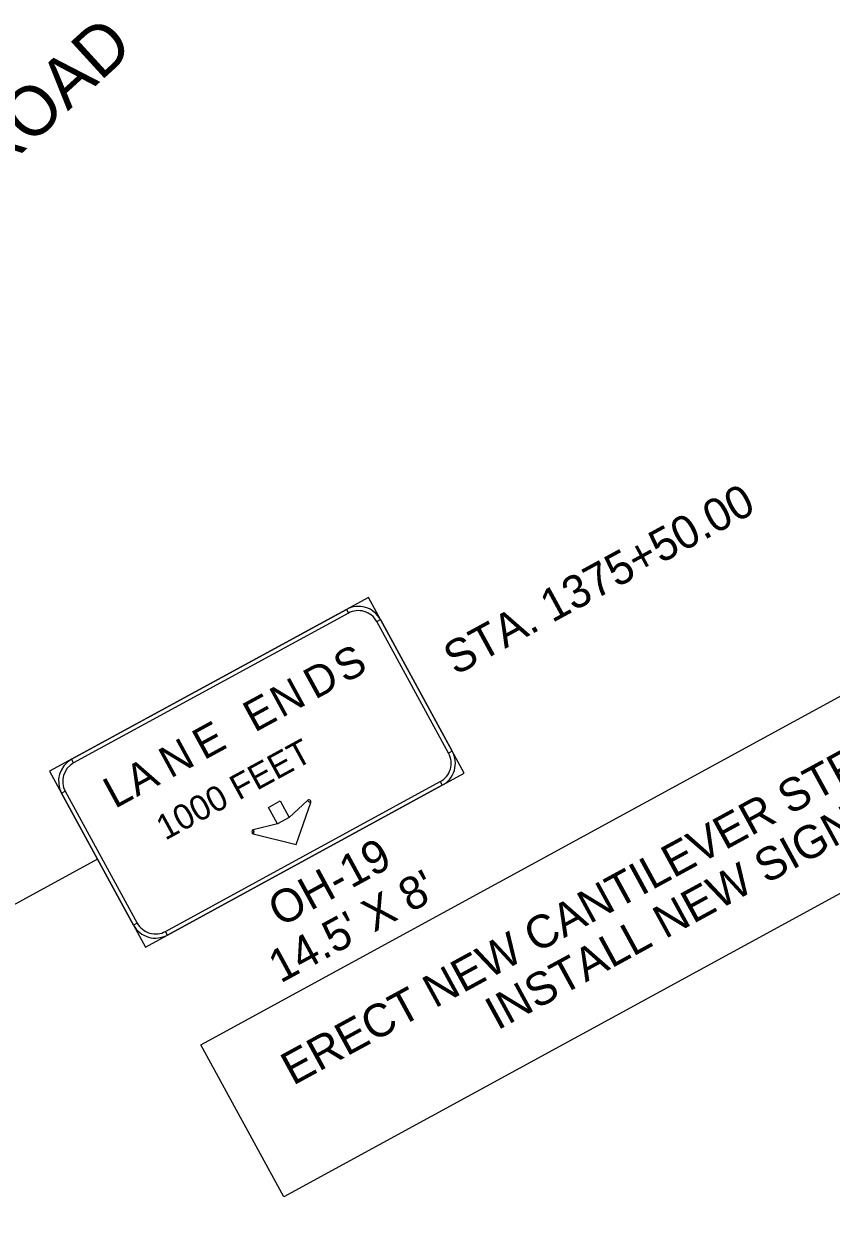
# Model space of a CAD drawing. Extents: x 2001876 to 2025694, y 804561 to 868938.
# Drawn here: x 2013356 to 2013846, y 824313 to 825035 of the extents above; entities that cross this region are included whole.
import ezdxf

# ---------------------------------------------------------------- set-up
doc = ezdxf.new("R2010")
doc.units = 0
for name, color, linetype in [('RD_TX_RoadID', 7, 'Continuous'), ('TR SN EXTRUDED PANEL SIGNS - GROUND MOUNTED', 7, 'Continuous'), ('TR SN EXTRUDED PANEL SIGNS- MOUNTED OVERHEAD', 7, 'Continuous')]:
    doc.layers.add(name, color=color, linetype=linetype)

msp = doc.modelspace()

# ---------------------------------------------------------------- linework, layer by layer
at = {"layer": 'TR SN EXTRUDED PANEL SIGNS - GROUND MOUNTED'}
for p, q in [((2013551.97, 824679.38), (2013553.18, 824677.16)), ((2013570.37, 824672.1), (2013572.59, 824673.31)), ((2013616.26, 824593.25), (2013614.04, 824592.04)), ((2013386.38, 824586.17), (2013385.17, 824588.4)), ((2013608.99, 824574.85), (2013610.2, 824572.63)), ((2013379.1, 824567.77), (2013381.33, 824568.99)), ((2013528.28, 824563.43), (2013529.15, 824562.51)), ((2013529.15, 824562.51), (2013530.35, 824562.11)), ((2013495.47, 824543.08), (2013495.79, 824544.31)), ((2013495.79, 824544.31), (2013495.48, 824545.54)), ((2013400.94, 824527.74), (2012949.03, 824281.24)), ((2013425, 824488.92), (2013422.78, 824487.71)), ((2013443.4, 824481.65), (2013442.18, 824483.87))]:
    msp.add_line(p, q, dxfattribs=at)
for points in [[(2013430.05, 824474.37), (2013623.54, 824579.91), (2013565.31, 824686.66), (2013371.83, 824581.12), (2013430.05, 824474.37)], [(2013553.18, 824677.16), (2013386.38, 824586.17), (2013385.17, 824588.4), (2013551.97, 824679.38), (2013553.18, 824677.16)], [(2013614.04, 824592.04), (2013570.37, 824672.1), (2013572.59, 824673.31), (2013616.26, 824593.25), (2013614.04, 824592.04)], [(2013442.18, 824483.87), (2013608.99, 824574.85), (2013610.2, 824572.63), (2013443.4, 824481.65), (2013442.18, 824483.87)], [(2013381.33, 824568.99), (2013425, 824488.92), (2013422.78, 824487.71), (2013379.1, 824567.77), (2013381.33, 824568.99)], [(2013521.57, 824536.73), (2013530.35, 824562.11), (2013529.15, 824562.51), (2013528.28, 824563.43), (2013517.3, 824553.15), (2013510.07, 824549.21), (2013495.48, 824545.54), (2013495.79, 824544.31), (2013495.47, 824543.08), (2013521.57, 824536.73)], [(2013504.61, 824559.22), (2013511.84, 824563.16), (2013517.3, 824553.15), (2013510.07, 824549.21), (2013504.61, 824559.22)]]:
    msp.add_lwpolyline(points, close=True, dxfattribs=at)
for centre, radius, start, end in [((2013559.25, 824666.04), 15.2, 28.61049, 118.6107), ((2013559.25, 824666.04), 12.67, 28.61049, 118.6107), ((2013602.92, 824585.97), 12.67, 298.61055, 28.61076), ((2013602.92, 824585.97), 15.2, 298.61055, 28.61076), ((2013392.45, 824575.05), 15.2, 118.6107, 208.61034), ((2013392.45, 824575.05), 12.67, 118.6107, 208.61034), ((2013529.15, 824562.51), 1.27, 341.63567, 133.08331), ((2013495.79, 824544.31), 1.27, 104.13779, 255.58543), ((2013436.12, 824494.99), 15.2, 208.61034, 298.61055), ((2013436.12, 824494.99), 12.67, 208.61034, 298.61055)]:
    msp.add_arc(centre, radius, start, end, dxfattribs=at)
at = {"layer": 'TR SN EXTRUDED PANEL SIGNS- MOUNTED OVERHEAD'}
msp.add_lwpolyline([(2013463.57, 824415.02), (2014004.74, 824710.2), (2014055.15, 824617.78), (2013513.98, 824322.6)], close=True, dxfattribs=at)

# ---------------------------------------------------------------- texts
at = {"layer": 'RD_TX_RoadID'}
msp.add_text('NORFOLK SOUTHERN RAILROAD', height=30, rotation=42.37827, dxfattribs=at).set_placement((2012946.49, 824583.75))
at = {"layer": 'TR SN EXTRUDED PANEL SIGNS - GROUND MOUNTED'}
for s, height, p in [('S', 19, (2013551.02, 824634.31)), ('D', 19, (2013532.93, 824624.44)), ('N', 19, (2013512.57, 824613.34)), ('E', 19, (2013496.27, 824604.45)), ('E', 19, (2013465.51, 824587.67)), ('1000 FEET', 15.2, (2013441.99, 824538.89)), ('N', 19, (2013445.15, 824576.57)), ('A', 19, (2013424.7, 824565.41)), ('L', 19, (2013411.42, 824558.17))]:
    msp.add_text(s, height=height, rotation=28.61049, dxfattribs=at).set_placement(p)
at = {"layer": 'TR SN EXTRUDED PANEL SIGNS- MOUNTED OVERHEAD'}
for s, p in [('STA. 1375+50.00', (2013618.16, 824639.05)), ('ERECT NEW CANTILEVER STRUCTURE.', (2013519.58, 824390.01)), ('INSTALL NEW SIGNS.', (2013643.67, 824423.53)), ('OH-19', (2013511.77, 824486.17)), ("14.5' X 8'", (2013511.93, 824452.08))]:
    msp.add_text(s, height=20, rotation=28.61049, dxfattribs=at).set_placement(p)

doc.saveas('drawing.dxf')
